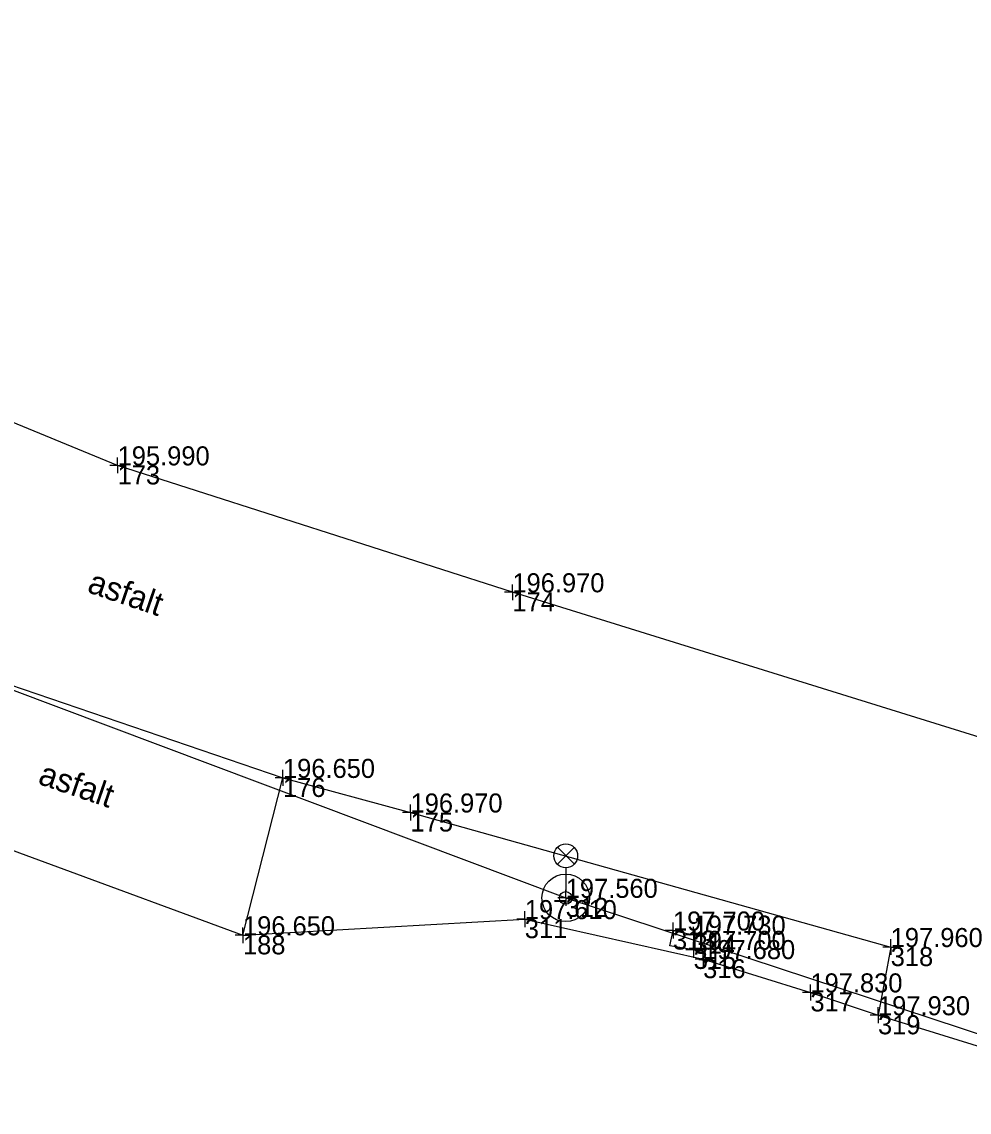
# Model space of a CAD drawing. Extents: x -744883 to -744469, y -966832 to -966374.
# Drawn here: x -744761.42 to -744731.57, y -966629.22 to -966594.86 of the extents above; entities that cross this region are included whole.
import ezdxf

# ---------------------------------------------------------------- set-up
doc = ezdxf.new("R2010")
doc.units = 0
for name, color, linetype in [('Body polohopisu', 7, 'Continuous'), ('Budovy', 7, 'Continuous'), ('Doplňkové značky', 7, 'Continuous'), ('Ploty_opěrné zdi', 7, 'Continuous'), ('Popisy objektů_povrchů', 7, 'Continuous'), ('Rozhraní ploch', 7, 'Continuous'), ('Vrstva 132', 7, 'Continuous'), ('Výšky bodů', 7, 'Continuous'), ('Značky IS', 7, 'Continuous'), ('Čísla bodů', 7, 'Continuous')]:
    doc.layers.add(name, color=color, linetype=linetype)

msp = doc.modelspace()

# ---------------------------------------------------------------- linework, layer by layer
at = {"layer": 'Body polohopisu'}
for p, q in [((-744758.4, -966608.84), (-744758.4, -966608.59)), ((-744758.4, -966608.84), (-744758.65, -966608.84)), ((-744758.4, -966608.84), (-744758.15, -966608.84)), ((-744758.4, -966608.84), (-744758.4, -966609.09)), ((-744745.96, -966612.84), (-744745.96, -966612.59)), ((-744745.96, -966612.84), (-744746.21, -966612.84)), ((-744745.96, -966612.84), (-744745.71, -966612.84)), ((-744745.96, -966612.84), (-744745.96, -966613.09)), ((-744753.19, -966618.69), (-744753.19, -966618.44)), ((-744753.19, -966618.69), (-744753.44, -966618.69)), ((-744753.19, -966618.69), (-744752.94, -966618.69)), ((-744753.19, -966618.69), (-744753.19, -966618.94)), ((-744749.17, -966619.78), (-744749.17, -966619.53)), ((-744749.17, -966619.78), (-744749.42, -966619.78)), ((-744749.17, -966619.78), (-744748.92, -966619.78)), ((-744749.17, -966619.78), (-744749.17, -966620.03)), ((-744744.28, -966622.47), (-744744.28, -966622.22)), ((-744744.28, -966622.47), (-744744.53, -966622.47)), ((-744744.28, -966622.47), (-744744.03, -966622.47)), ((-744744.28, -966622.47), (-744744.28, -966622.72)), ((-744745.57, -966623.14), (-744745.57, -966622.89)), ((-744745.57, -966623.14), (-744745.82, -966623.14)), ((-744745.57, -966623.14), (-744745.32, -966623.14)), ((-744745.57, -966623.14), (-744745.57, -966623.39)), ((-744740.9, -966623.5), (-744740.9, -966623.25)), ((-744740.25, -966623.63), (-744740.25, -966623.38)), ((-744754.45, -966623.65), (-744754.7, -966623.65)), ((-744754.45, -966623.65), (-744754.45, -966623.4)), ((-744754.45, -966623.65), (-744754.2, -966623.65)), ((-744754.45, -966623.65), (-744754.45, -966623.9)), ((-744740.9, -966623.5), (-744741.15, -966623.5)), ((-744740.9, -966623.5), (-744740.65, -966623.5)), ((-744740.9, -966623.5), (-744740.9, -966623.75)), ((-744740.25, -966623.63), (-744740.5, -966623.63)), ((-744740.25, -966623.63), (-744740, -966623.63)), ((-744740.25, -966623.63), (-744740.25, -966623.88)), ((-744740.25, -966624.11), (-744740.25, -966623.86)), ((-744734.04, -966624.02), (-744734.29, -966624.02)), ((-744734.04, -966624.02), (-744734.04, -966623.77)), ((-744734.04, -966624.02), (-744733.79, -966624.02)), ((-744734.04, -966624.02), (-744734.04, -966624.27)), ((-744740.25, -966624.11), (-744740.5, -966624.11)), ((-744740.25, -966624.11), (-744740, -966624.11)), ((-744740.25, -966624.11), (-744740.25, -966624.36)), ((-744739.95, -966624.4), (-744740.2, -966624.4)), ((-744739.95, -966624.4), (-744739.95, -966624.15)), ((-744739.95, -966624.4), (-744739.7, -966624.4)), ((-744739.95, -966624.4), (-744739.95, -966624.65)), ((-744736.57, -966625.45), (-744736.57, -966625.2)), ((-744736.57, -966625.45), (-744736.82, -966625.45)), ((-744736.57, -966625.45), (-744736.32, -966625.45)), ((-744736.57, -966625.45), (-744736.57, -966625.7)), ((-744734.44, -966626.17), (-744734.44, -966625.92)), ((-744734.44, -966626.17), (-744734.69, -966626.17)), ((-744734.44, -966626.17), (-744734.19, -966626.17)), ((-744734.44, -966626.17), (-744734.44, -966626.42))]:
    msp.add_line(p, q, dxfattribs=at)
at = {"layer": 'Budovy'}
msp.add_lwpolyline([(-744776.06, -966615.8), (-744771.28, -966617.48), (-744766.54, -966619.19), (-744754.45, -966623.65)], dxfattribs=at)
at = {"layer": 'Doplňkové značky'}
for p, q in [((-744744.544, -966621.408), (-744744.016, -966620.88)), ((-744744.008, -966621.405), (-744744.536, -966620.876)), ((-744744.28, -966621.52), (-744744.28, -966622.27))]:
    msp.add_line(p, q, dxfattribs=at)
for centre, radius in [((-744744.28, -966621.145), 0.375), ((-744744.28, -966622.47), 0.2)]:
    msp.add_circle(centre, radius, dxfattribs=at)
at = {"layer": 'Ploty_opěrné zdi'}
for points in [[(-744754.45, -966623.65), (-744745.57, -966623.14), (-744739.95, -966624.4), (-744736.57, -966625.45), (-744734.44, -966626.17)], [(-744734.44, -966626.17), (-744722.49, -966629.87)]]:
    msp.add_lwpolyline(points, dxfattribs=at)
at = {"layer": 'Rozhraní ploch'}
for points in [[(-744656.07, -966650.16), (-744662.8, -966644.01), (-744672.73, -966638.23), (-744685.11, -966632.67), (-744699.67, -966627.63), (-744718.38, -966621.41), (-744745.96, -966612.84), (-744758.4, -966608.84), (-744770.58, -966603.83), (-744782.97, -966596.56), (-744784.85, -966594.86)], [(-744764.83, -966614.72), (-744753.19, -966618.69)], [(-744754.45, -966623.65), (-744753.19, -966618.69), (-744749.17, -966619.78), (-744734.04, -966624.02), (-744734.44, -966626.17)]]:
    msp.add_lwpolyline(points, dxfattribs=at)
at = {"layer": 'Vrstva 132'}
msp.add_lwpolyline([(-744784.17, -966607.48), (-744744.28, -966622.47), (-744705.89, -966635.13)], dxfattribs=at)
at = {"layer": 'Značky IS'}
msp.add_lwpolyline([(-744740.9, -966623.5), (-744740.25, -966623.63), (-744740.25, -966624.11), (-744741.005, -966623.984), (-744740.9, -966623.5)], dxfattribs=at)
msp.add_circle((-744744.28, -966622.47), 0.75, dxfattribs=at)

# ---------------------------------------------------------------- texts
at = {"layer": 'Popisy objektů_povrchů'}
for p in [(-744759.392, -966612.824), (-744760.943, -966618.865)]:
    msp.add_text('asfalt', height=0.75, rotation=341.1673, dxfattribs=at).set_placement(p)
at = {"layer": 'Výšky bodů'}
for s, p in [('195.990', (-744758.4, -966608.84)), ('196.970', (-744745.96, -966612.84)), ('196.650', (-744753.19, -966618.69)), ('196.970', (-744749.17, -966619.78)), ('197.560', (-744744.28, -966622.47)), ('197.610', (-744745.57, -966623.14)), ('197.700', (-744740.9, -966623.5)), ('197.730', (-744740.25, -966623.63)), ('196.650', (-744754.45, -966623.65)), ('197.700', (-744740.25, -966624.11)), ('197.960', (-744734.04, -966624.02)), ('197.680', (-744739.95, -966624.4)), ('197.830', (-744736.57, -966625.45)), ('197.930', (-744734.44, -966626.17))]:
    msp.add_text(s, height=0.6, dxfattribs=at).set_placement(p)
at = {"layer": 'Čísla bodů'}
for s, p in [('173', (-744758.4, -966609.44)), ('174', (-744745.96, -966613.44)), ('176', (-744753.19, -966619.29)), ('175', (-744749.17, -966620.38)), ('312', (-744744.28, -966623.07)), ('311', (-744745.57, -966623.74)), ('188', (-744754.45, -966624.25)), ('313', (-744740.9, -966624.1)), ('314', (-744740.25, -966624.23)), ('318', (-744734.04, -966624.62)), ('315', (-744740.25, -966624.71)), ('316', (-744739.95, -966625)), ('317', (-744736.57, -966626.05)), ('319', (-744734.44, -966626.77))]:
    msp.add_text(s, height=0.6, dxfattribs=at).set_placement(p)

doc.saveas('drawing.dxf')
